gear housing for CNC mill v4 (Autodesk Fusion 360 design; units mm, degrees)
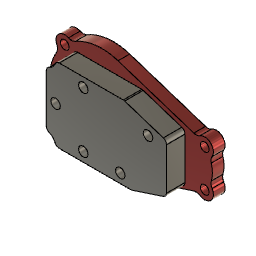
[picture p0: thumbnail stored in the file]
description: Gear Housing Assembly
derived_base_feature "Derived Base Feature1"
derived_base_feature "Derived Base Feature1" bodies "Front Housing"
derived_base_feature "Derived Base Feature1" bodies "Front Cover"
derived_base_feature "Derived Base Feature1" bodies "Back Housing"
as_built_joint "As-built1"
offset_faces "OffsetFaces1" distance 5
delete_face "DeleteFace1"
delete_face "DeleteFace2"
sketch "Sketch1" plane through (0, -21, 0) normal (0, -1, 0) x axis (1, 0, 0)
  line L1 (11.1724, 34.2225) -> (63.2283, 17.2281)
  line L2 (63.2283, -17.2281) -> (11.1724, -34.2225)
  arc A1 centre (64.7801, 21.9812) radius 5 clockwise from (67.4836, 17.7752) to (63.2283, 17.2281)
  arc A2 centre (0, 0) radius 36 clockwise from (-18.189, 31.067) to (11.1724, 34.2225)
  arc A3 centre (-20.7152, 35.3819) radius 5 clockwise from (-18.189, 31.067) to (-22.8701, 30.8701)
  arc A4 centre (-25.4558, 25.4558) radius 6 clockwise from (-30.8701, 22.8701) to (-22.8701, 30.8701)
  arc A5 centre (-35.3819, 20.7152) radius 5 clockwise from (-30.8701, 22.8701) to (-31.067, 18.189)
  arc A6 centre (0, 0) radius 36 clockwise from (-31.067, -18.189) to (-31.067, 18.189)
  arc A7 centre (-35.3819, -20.7152) radius 5 clockwise from (-31.067, -18.189) to (-30.8701, -22.8701)
  arc A8 centre (-25.4558, -25.4558) radius 6 clockwise from (-22.8701, -30.8701) to (-30.8701, -22.8701)
  arc A9 centre (-20.7152, -35.3819) radius 5 clockwise from (-22.8701, -30.8701) to (-18.189, -31.067)
  arc A10 centre (0, 0) radius 36 clockwise from (11.1724, -34.2225) to (-18.189, -31.067)
  arc A11 centre (64.7801, -21.9812) radius 5 clockwise from (63.2283, -17.2281) to (67.4836, -17.7752)
  arc A12 centre (70.7279, -12.7279) radius 6 clockwise from (75.774, -9.4818) to (67.4836, -17.7752)
  arc A13 centre (79.979, -6.7767) radius 5 clockwise from (75.774, -9.4818) to (75.201, -5.3035)
  arc A14 centre (58, 0) radius 18 clockwise from (75.201, 5.3035) to (75.201, -5.3035)
  arc A15 centre (79.979, 6.7767) radius 5 clockwise from (75.201, 5.3035) to (75.774, 9.4818)
  arc A16 centre (70.7279, 12.7279) radius 6 clockwise from (67.4836, 17.7752) to (75.774, 9.4818)
  circle C1 centre (70.7279, -12.7279) radius 3
  circle C2 centre (70.7279, 12.7279) radius 3
  circle C3 centre (-25.4558, -25.4558) radius 3
  circle C4 centre (-25.4558, 25.4558) radius 3
  circle C5 centre (0, 0) radius 5.25
  circle C6 centre (0, 0) radius 19.05
  point P1 (0, 0)
  point P34 (0, 0)
  point P35 (0, -19.05)
  point P36 (-19.05, 0)
  point P37 (0, 19.05)
  point P38 (44.45, 12.7)
  point P39 (25.4, -19.05)
  coincident P1 P34
  coincident C6 P35
  coincident C6 P36
  coincident C6 P37
  vertical P34 P35
  horizontal P1 P36
  vertical P1 P37
  dimension "d2" diameter C6 = 38.1
  dimension "d3" distance P1 P38 = 44.45
  dimension "d4" distance P1 P38 = 12.7
  dimension "d5" distance P34 P39 = 25.4
  dimension "d6" distance P34 P39 = 19.05
hole "Hole1" HoleDepth 5.715 HoleDiameter 5.1308 TipAngle 118
ground "Ground1"
ground "Ground2"
ground "Ground3"
ground "Ground4"
position "Position1"
sketch "Sketch1" plane through (0, 0, 0) normal (0, 1, 0) x axis (1, 0, 0)
  line L1 (57.15, -25.4) -> (-25.4, -25.4)
  line L2 (57.15, 25.4) -> (57.15, -25.4)
  line L3 (-25.4, 25.4) -> (57.15, 25.4)
  line L4 (-25.4, -25.4) -> (-25.4, 25.4)
  line L5 (11.1724, -34.2225) -> (63.2283, -17.2281)
  line L6 (63.2283, 17.2281) -> (11.1724, 34.2225)
  line L7 (10.1871, -31.2042) -> (62.243, -14.2098)
  line L8 (62.7357, 15.719) -> (10.6797, 32.7134)
  circle C1 centre (-25.4558, -25.4558) radius 3
  circle C2 centre (-25.4558, 25.4558) radius 3
  circle C3 centre (-25.4558, -25.4558) radius 6.35
  circle C4 centre (-25.4558, 25.4558) radius 6.35
  point P1 (0, 0)
  horizontal L1
  vertical L2
  horizontal L3
  vertical L4
  concentric C1 C3
  concentric C2 C4
  equal C3 C4
  dimension "d10" distance P1 L1 = 25.4
  dimension "d11" distance P1 L3 = 25.4 (= "d10")
  dimension "d12" distance P1 L2 = 57.15
  dimension "d13" distance P1 L4 = 25.4
  dimension "d14" diameter C3 = 12.7
  dimension "d15" = 3.175
  dimension "d16" = 1.5875
extrude "Extrude1" new body sketch "Sketch1" profile of L1 L2 L3 L4 C3 C4 L7 L8 against normal blind 12.7
fillet "Fillet1" radius 3.175
hole "Hole1" HoleDepth 12.7 HoleDiameter 6.477 TipAngle 118
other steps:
thread "Thread1"
create_component "CreateComponent1"
create_component "CreateComponent5"
create_component "CreateComponent1"
create_component "CreateComponent2"
create_component "CreateComponent3"
named bodies: "Back Housing", "Front Cover", "Front Housing"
